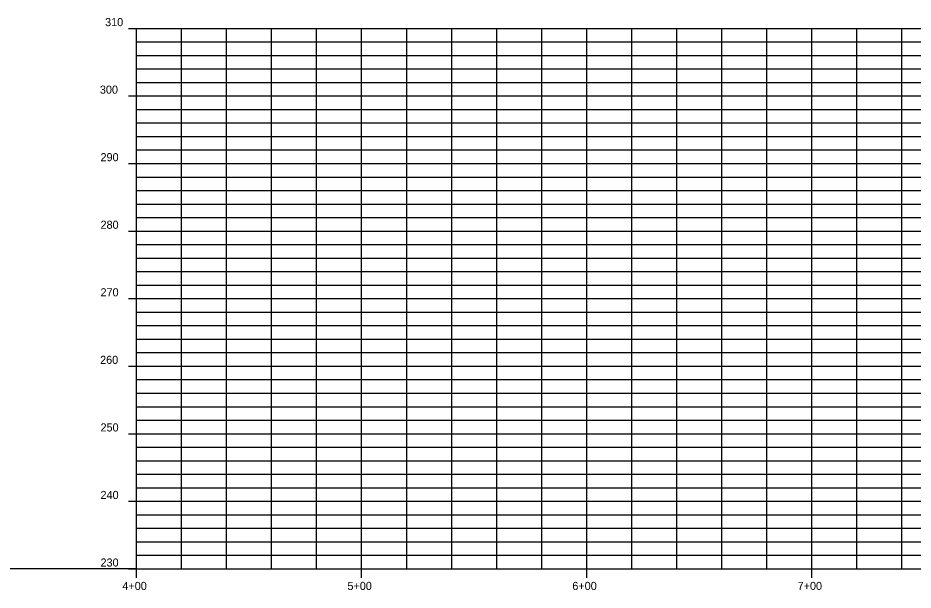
# Model space of a CAD drawing. Extents: x 1709196 to 1718257, y 543790 to 550544.
# Drawn here: x 1710712.6 to 1711110.3, y 546661.1 to 546915.2 of the extents above; entities that cross this region are included whole.
import ezdxf

# ---------------------------------------------------------------- set-up
doc = ezdxf.new("R2010")
doc.units = 0
for name, color, linetype in [('R_Axis', 7, 'Continuous'), ('R_Axis Annot', 7, 'Continuous'), ('R_Grid', 7, 'Continuous'), ('R_No Plot', 7, 'Continuous')]:
    doc.layers.add(name, color=color, linetype=linetype)

msp = doc.modelspace()

# ---------------------------------------------------------------- linework, layer by layer
at = {"layer": 'R_Axis'}
for q in [(1710765.3, 546910.52), (1711665.3, 546670.52)]:
    msp.add_line((1710765.3, 546670.52), q, dxfattribs=at)
at = {"layer": 'R_Grid'}
for p, q in [((1710761.7, 546910.52), (1710765.3, 546910.52)), ((1710761.7, 546910.52), (1710765.3, 546910.52)), ((1710765.3, 546910.52), (1711665.3, 546910.52)), ((1710765.3, 546910.52), (1711665.3, 546910.52)), ((1710785.3, 546670.52), (1710785.3, 546910.52)), ((1710805.3, 546670.52), (1710805.3, 546910.52)), ((1710825.3, 546670.52), (1710825.3, 546910.52)), ((1710845.3, 546670.52), (1710845.3, 546910.52)), ((1710865.3, 546670.52), (1710865.3, 546910.52)), ((1710885.3, 546670.52), (1710885.3, 546910.52)), ((1710905.3, 546670.52), (1710905.3, 546910.52)), ((1710925.3, 546670.52), (1710925.3, 546910.52)), ((1710945.3, 546670.52), (1710945.3, 546910.52)), ((1710965.3, 546670.52), (1710965.3, 546910.52)), ((1710985.3, 546670.52), (1710985.3, 546910.52)), ((1711005.3, 546670.52), (1711005.3, 546910.52)), ((1711025.3, 546670.52), (1711025.3, 546910.52)), ((1711045.3, 546670.52), (1711045.3, 546910.52)), ((1711065.3, 546670.52), (1711065.3, 546910.52)), ((1711085.3, 546670.52), (1711085.3, 546910.52)), ((1711105.3, 546670.52), (1711105.3, 546910.52)), ((1710765.3, 546904.52), (1710767.1, 546904.52)), ((1710765.3, 546904.52), (1711665.3, 546904.52)), ((1710765.3, 546898.52), (1710767.1, 546898.52)), ((1710765.3, 546898.52), (1711665.3, 546898.52)), ((1710765.3, 546892.52), (1710767.1, 546892.52)), ((1710765.3, 546892.52), (1711665.3, 546892.52)), ((1710765.3, 546886.52), (1710767.1, 546886.52)), ((1710765.3, 546886.52), (1711665.3, 546886.52)), ((1710761.7, 546880.52), (1710765.3, 546880.52)), ((1710765.3, 546880.52), (1711665.3, 546880.52)), ((1710765.3, 546874.52), (1710767.1, 546874.52)), ((1710765.3, 546874.52), (1711665.3, 546874.52)), ((1710765.3, 546868.52), (1710767.1, 546868.52)), ((1710765.3, 546868.52), (1711665.3, 546868.52)), ((1710765.3, 546862.52), (1710767.1, 546862.52)), ((1710765.3, 546862.52), (1711665.3, 546862.52)), ((1710765.3, 546856.52), (1710767.1, 546856.52)), ((1710765.3, 546856.52), (1711665.3, 546856.52)), ((1710761.7, 546850.52), (1710765.3, 546850.52)), ((1710765.3, 546850.52), (1711665.3, 546850.52)), ((1710765.3, 546844.52), (1710767.1, 546844.52)), ((1710765.3, 546844.52), (1711665.3, 546844.52)), ((1710765.3, 546838.52), (1710767.1, 546838.52)), ((1710765.3, 546838.52), (1711665.3, 546838.52)), ((1710765.3, 546832.52), (1710767.1, 546832.52)), ((1710765.3, 546832.52), (1711665.3, 546832.52)), ((1710765.3, 546826.52), (1710767.1, 546826.52)), ((1710765.3, 546826.52), (1711665.3, 546826.52)), ((1710761.7, 546820.52), (1710765.3, 546820.52)), ((1710765.3, 546820.52), (1711665.3, 546820.52)), ((1710765.3, 546814.52), (1710767.1, 546814.52)), ((1710765.3, 546814.52), (1711665.3, 546814.52)), ((1710765.3, 546808.52), (1710767.1, 546808.52)), ((1710765.3, 546808.52), (1711665.3, 546808.52)), ((1710765.3, 546802.52), (1710767.1, 546802.52)), ((1710765.3, 546802.52), (1711665.3, 546802.52)), ((1710765.3, 546796.52), (1710767.1, 546796.52)), ((1710765.3, 546796.52), (1711665.3, 546796.52)), ((1710761.7, 546790.52), (1710765.3, 546790.52)), ((1710765.3, 546790.52), (1711665.3, 546790.52)), ((1710765.3, 546784.52), (1710767.1, 546784.52)), ((1710765.3, 546784.52), (1711665.3, 546784.52)), ((1710765.3, 546778.52), (1710767.1, 546778.52)), ((1710765.3, 546778.52), (1711665.3, 546778.52)), ((1710765.3, 546772.52), (1710767.1, 546772.52)), ((1710765.3, 546772.52), (1711665.3, 546772.52)), ((1710765.3, 546766.52), (1710767.1, 546766.52)), ((1710765.3, 546766.52), (1711665.3, 546766.52)), ((1710761.7, 546760.52), (1710765.3, 546760.52)), ((1710765.3, 546760.52), (1711665.3, 546760.52)), ((1710765.3, 546754.52), (1710767.1, 546754.52)), ((1710765.3, 546754.52), (1711665.3, 546754.52)), ((1710765.3, 546748.52), (1710767.1, 546748.52)), ((1710765.3, 546748.52), (1711665.3, 546748.52)), ((1710765.3, 546742.52), (1710767.1, 546742.52)), ((1710765.3, 546742.52), (1711665.3, 546742.52)), ((1710765.3, 546736.52), (1710767.1, 546736.52)), ((1710765.3, 546736.52), (1711665.3, 546736.52)), ((1710761.7, 546730.52), (1710765.3, 546730.52)), ((1710765.3, 546730.52), (1711665.3, 546730.52)), ((1710765.3, 546724.52), (1710767.1, 546724.52)), ((1710765.3, 546724.52), (1711665.3, 546724.52)), ((1710765.3, 546718.52), (1710767.1, 546718.52)), ((1710765.3, 546718.52), (1711665.3, 546718.52)), ((1710765.3, 546712.52), (1710767.1, 546712.52)), ((1710765.3, 546712.52), (1711665.3, 546712.52)), ((1710765.3, 546706.52), (1710767.1, 546706.52)), ((1710765.3, 546706.52), (1711665.3, 546706.52)), ((1710761.7, 546700.52), (1710765.3, 546700.52)), ((1710765.3, 546700.52), (1711665.3, 546700.52)), ((1710765.3, 546694.52), (1710767.1, 546694.52)), ((1710765.3, 546694.52), (1711665.3, 546694.52)), ((1710765.3, 546688.52), (1710767.1, 546688.52)), ((1710765.3, 546688.52), (1711665.3, 546688.52)), ((1710765.3, 546682.52), (1710767.1, 546682.52)), ((1710765.3, 546682.52), (1711665.3, 546682.52)), ((1710765.3, 546676.52), (1710767.1, 546676.52)), ((1710765.3, 546676.52), (1711665.3, 546676.52)), ((1710761.7, 546670.52), (1710765.3, 546670.52)), ((1710765.3, 546666.52), (1710765.3, 546670.52)), ((1710865.3, 546666.52), (1710865.3, 546670.52)), ((1710965.3, 546666.52), (1710965.3, 546670.52)), ((1711065.3, 546666.52), (1711065.3, 546670.52))]:
    msp.add_line(p, q, dxfattribs=at)
at = {"layer": 'R_No Plot'}
msp.add_line((1710765.3, 546670.52), (1709196.12, 546670.52), dxfattribs=at)

# ---------------------------------------------------------------- texts
at = {"layer": 'R_Axis Annot'}
for s, height, p in [('310', 3.6, (1710751.32, 546911.52)), ('310', 3.6, (1710751.32, 546911.52)), ('300', 3.6, (1710749, 546881.52)), ('290', 3.6, (1710749.28, 546851.52)), ('280', 3.6, (1710749.28, 546821.52)), ('270', 3.6, (1710749.28, 546791.52)), ('260', 3.6, (1710749.11, 546761.52)), ('250', 3.6, (1710749.28, 546731.52)), ('240', 3.6, (1710749.28, 546701.52)), ('230', 3.6, (1710749.28, 546671.52)), ('-', 0.0001, (1710765.3, 546670.52)), ('4+00', 3.6, (1710758.99, 546661.12)), ('5+00', 3.6, (1710858.99, 546661.12)), ('6+00', 3.6, (1710958.9, 546661.12)), ('7+00', 3.6, (1711058.99, 546661.12))]:
    msp.add_text(s, height=height, dxfattribs=at).set_placement(p)

doc.saveas('drawing.dxf')
